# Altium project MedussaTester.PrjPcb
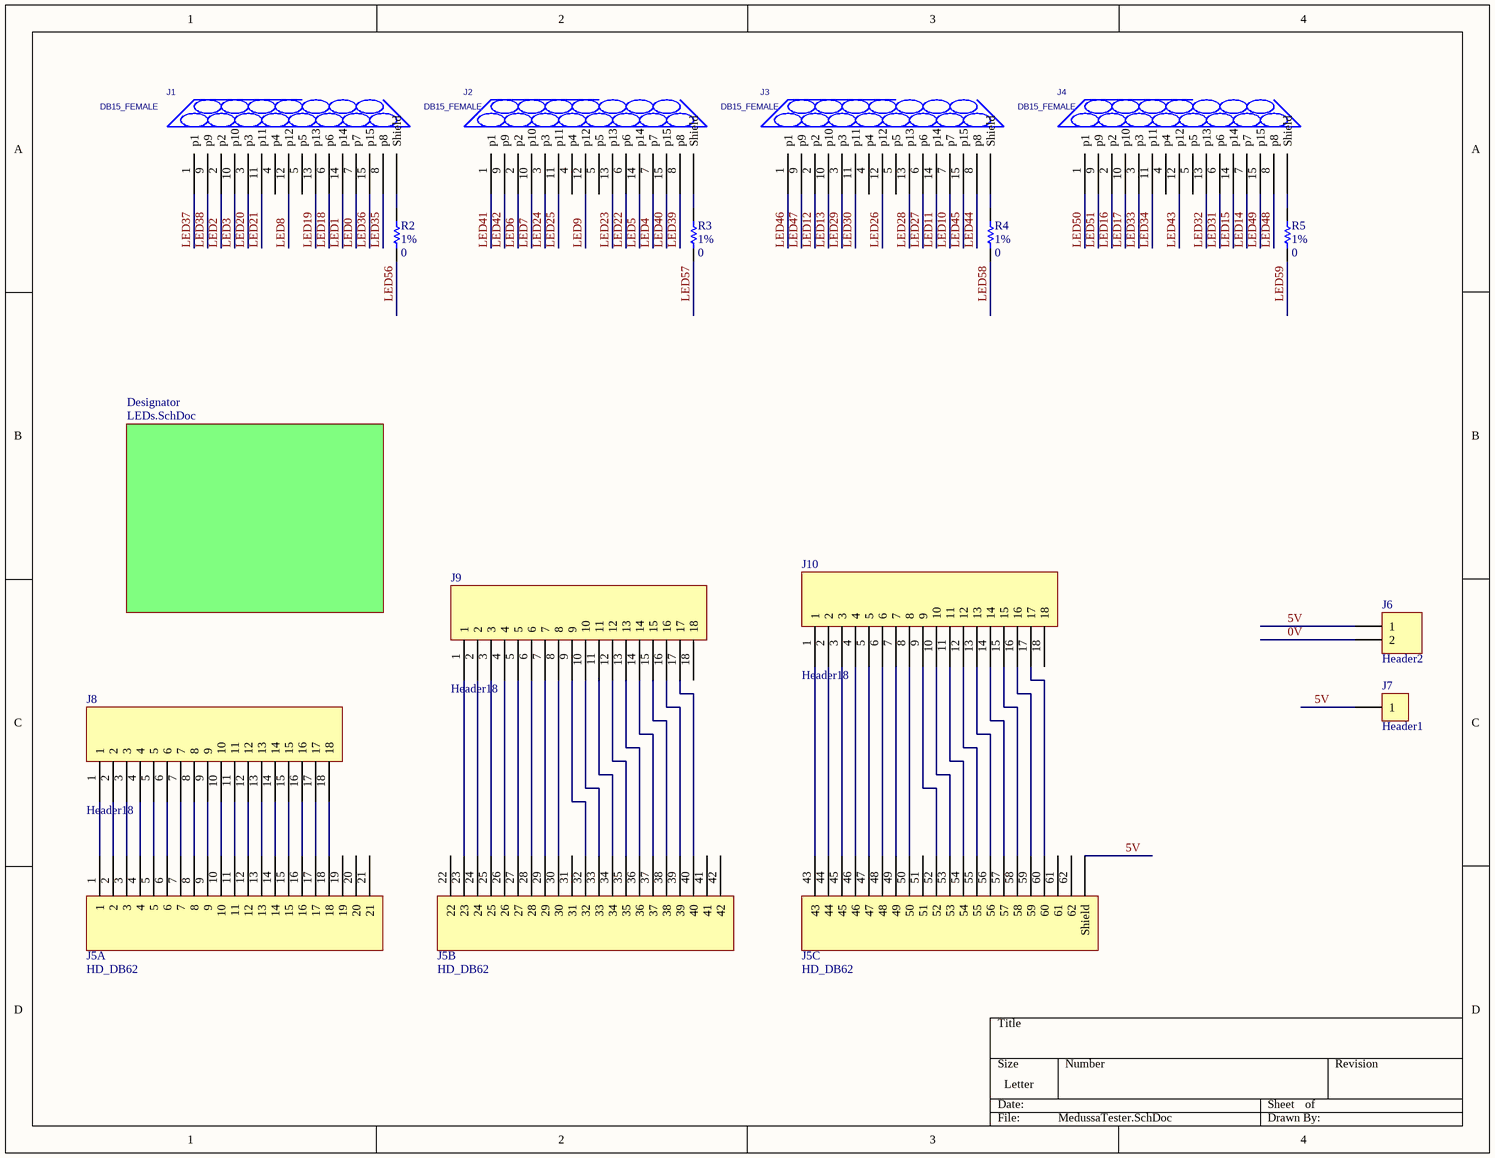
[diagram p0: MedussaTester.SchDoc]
2 sheets, 21 parts. Net scope: global (net labels, ports and power ports of the same name join across sheets).
Board file: MadussaTester.PcbDoc
Sheets:
  MedussaTester.SchDoc
    Designator = LEDs.SchDoc

## Sheet MedussaTester.SchDoc
size Letter

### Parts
J1  DB15_FEMALE  [DSUB/RS.318/TM/15]
J2  DB15_FEMALE  [DSUB/RS.318/TM/15]
J3  DB15_FEMALE  [DSUB/RS.318/TM/15]
J4  DB15_FEMALE  [DSUB/RS.318/TM/15]
J5  HD_DB62  [HD_DB62]  (parts A,B,C of 3)
J6  Header2  [HDR1X2]
J7  Header1  [HDR1]
J8  Header18  [HDR1X18]
J9  Header18  [HDR1X18]
J10  Header18  [HDR1X18]
R2  value 0  Param: 1%  [0603]  (hidden comment: 10k Ohms)
R3  value 0  Param: 1%  [0603]  (hidden comment: 10k Ohms)
R4  value 0  Param: 1%  [0603]  (hidden comment: 10k Ohms)
R5  value 0  Param: 1%  [0603]  (hidden comment: 10k Ohms)

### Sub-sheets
Designator = LEDs.SchDoc: no entries

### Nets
0V: J6.2
5V: J5.HOLE63(Shield) J6.1 J7.1
LED0: J1.7(p7)
LED1: J1.14(p14)
LED2: J1.2(p2)
LED3: J1.10(p10)
LED4: J2.7(p7)
LED5: J2.14(p14)
LED6: J2.2(p2)
LED7: J2.10(p10)
LED8: J1.12(p12)
LED9: J2.12(p12)
LED10: J3.7(p7)
LED11: J3.14(p14)
LED12: J3.2(p2)
LED13: J3.10(p10)
LED14: J4.7(p7)
LED15: J4.14(p14)
LED16: J4.2(p2)
LED17: J4.10(p10)
LED18: J1.6(p6)
LED19: J1.13(p13)
LED20: J1.3(p3)
LED21: J1.11(p11)
LED22: J2.6(p6)
LED23: J2.13(p13)
LED24: J2.3(p3)
LED25: J2.11(p11)
LED26: J3.12(p12)
LED27: J3.6(p6)
LED28: J3.13(p13)
LED29: J3.3(p3)
LED30: J3.11(p11)
LED31: J4.6(p6)
LED32: J4.13(p13)
LED33: J4.3(p3)
LED34: J4.11(p11)
LED35: J1.8(p8)
LED36: J1.15(p15)
LED37: J1.1(p1)
LED38: J1.9(p9)
LED39: J2.8(p8)
LED40: J2.15(p15)
LED41: J2.1(p1)
LED42: J2.9(p9)
LED43: J4.12(p12)
LED44: J3.8(p8)
LED45: J3.15(p15)
LED46: J3.1(p1)
LED47: J3.9(p9)
LED48: J4.8(p8)
LED49: J4.15(p15)
LED50: J4.1(p1)
LED51: J4.9(p9)
LED56: R2.1
LED57: R3.1
LED58: R4.1
LED59: R5.1
NetJ1_Hole30: J1.Hole30(Shield) R2.2
NetJ2_Hole30: J2.Hole30(Shield) R3.2
NetJ3_Hole30: J3.Hole30(Shield) R4.2
NetJ4_Hole30: J4.Hole30(Shield) R5.2
NetJ5_1: J5.1 J8.1
NetJ5_2: J5.2 J8.2
NetJ5_3: J5.3 J8.3
NetJ5_4: J5.4 J8.4
NetJ5_5: J5.5 J8.5
NetJ5_6: J5.6 J8.6
NetJ5_7: J5.7 J8.7
NetJ5_8: J5.8 J8.8
NetJ5_9: J5.9 J8.9
NetJ5_10: J5.10 J8.10
NetJ5_11: J5.11 J8.11
NetJ5_12: J5.12 J8.12
NetJ5_13: J5.13 J8.13
NetJ5_14: J5.14 J8.14
NetJ5_15: J5.15 J8.15
NetJ5_16: J5.16 J8.16
NetJ5_17: J5.17 J8.17
NetJ5_18: J5.18 J8.18
NetJ5_23: J5.23 J9.1
NetJ5_24: J5.24 J9.2
NetJ5_25: J5.25 J9.3
NetJ5_26: J5.26 J9.4
NetJ5_27: J5.27 J9.5
NetJ5_28: J5.28 J9.6
NetJ5_29: J5.29 J9.7
NetJ5_30: J5.30 J9.8
NetJ5_32: J5.32 J9.9
NetJ5_33: J5.33 J9.10
NetJ5_34: J5.34 J9.11
NetJ5_35: J5.35 J9.12
NetJ5_36: J5.36 J9.13
NetJ5_37: J5.37 J9.14
NetJ5_38: J5.38 J9.15
NetJ5_39: J5.39 J9.16
NetJ5_40: J5.40 J9.17
NetJ5_43: J5.43 J10.1
NetJ5_44: J5.44 J10.2
NetJ5_45: J5.45 J10.3
NetJ5_46: J5.46 J10.4
NetJ5_47: J5.47 J10.5
NetJ5_48: J5.48 J10.6
NetJ5_49: J5.49 J10.7
NetJ5_50: J5.50 J10.8
NetJ5_52: J5.52 J10.9
NetJ5_53: J5.53 J10.10
NetJ5_54: J5.54 J10.11
NetJ5_55: J5.55 J10.12
NetJ5_56: J5.56 J10.13
NetJ5_57: J5.57 J10.14
NetJ5_58: J5.58 J10.15
NetJ5_59: J5.59 J10.16
NetJ5_60: J5.60 J10.17

Not connected (* = marked no-connect by the designer): J1 4(p4) 5(p5); J2 4(p4) 5(p5); J3 4(p4) 5(p5); J4 4(p4) 5(p5); J5 19 20 21 22 31 41 42 51 61 62; J9 18; J10 18

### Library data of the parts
J1-J4 = DB15_FEMALE: COMPFIXED: NO; COMPGROUP: 0; COMPHEIGHT: 0.000; COMPLOC: [4502.733,1338.467]; COMPROT: 270; COMPSIDE: TOP
J7 = Header1: TestPoint1
R2-R5 = Res0603: Resistor; Param1: 100ppm/C

## Sheet LEDs.SchDoc
size Letter
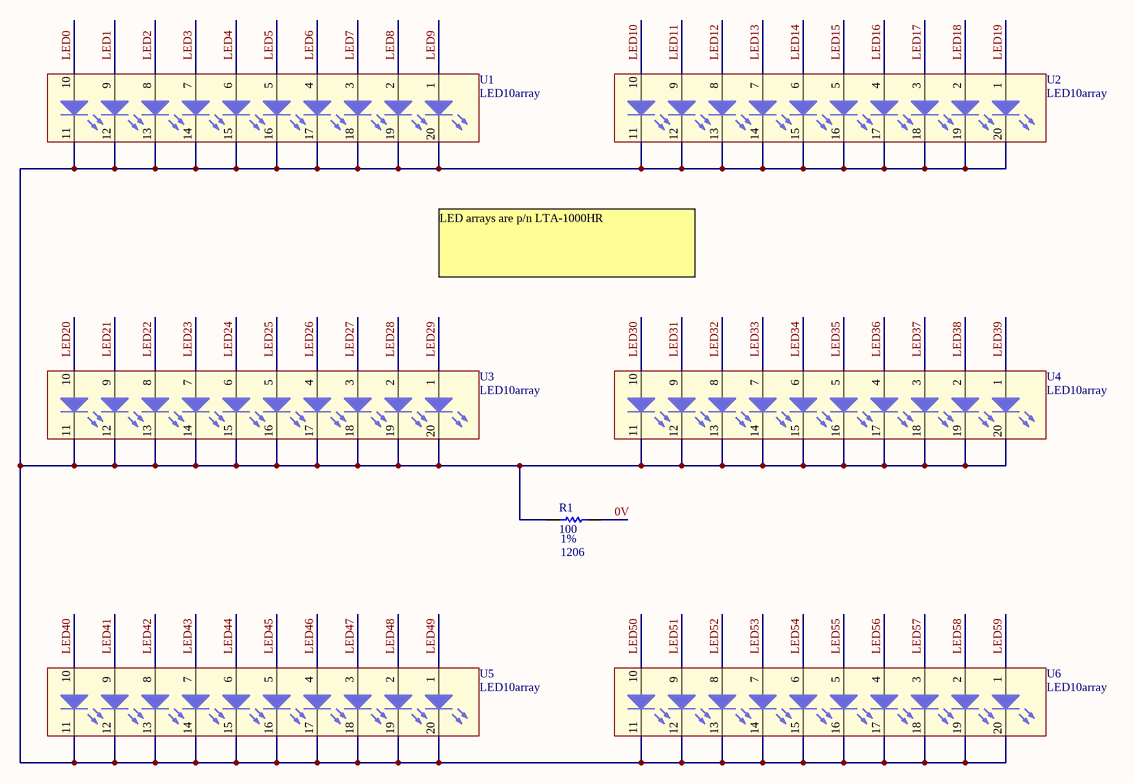
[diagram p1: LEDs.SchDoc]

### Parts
R1  100  Param: 1%  [1206]
U1  LED10array  [LED10array]
U2  LED10array  [LED10array]
U3  LED10array  [LED10array]
U4  LED10array  [LED10array]
U5  LED10array  [LED10array]
U6  LED10array  [LED10array]

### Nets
0V: R1.2
LED0: U1.10
LED1: U1.9
LED2: U1.8
LED3: U1.7
LED4: U1.6
LED5: U1.5
LED6: U1.4
LED7: U1.3
LED8: U1.2
LED9: U1.1
LED10: U2.10
LED11: U2.9
LED12: U2.8
LED13: U2.7
LED14: U2.6
LED15: U2.5
LED16: U2.4
LED17: U2.3
LED18: U2.2
LED19: U2.1
LED20: U3.10
LED21: U3.9
LED22: U3.8
LED23: U3.7
LED24: U3.6
LED25: U3.5
LED26: U3.4
LED27: U3.3
LED28: U3.2
LED29: U3.1
LED30: U4.10
LED31: U4.9
LED32: U4.8
LED33: U4.7
LED34: U4.6
LED35: U4.5
LED36: U4.4
LED37: U4.3
LED38: U4.2
LED39: U4.1
LED40: U5.10
LED41: U5.9
LED42: U5.8
LED43: U5.7
LED44: U5.6
LED45: U5.5
LED46: U5.4
LED47: U5.3
LED48: U5.2
LED49: U5.1
LED50: U6.10
LED51: U6.9
LED52: U6.8
LED53: U6.7
LED54: U6.6
LED55: U6.5
LED56: U6.4
LED57: U6.3
LED58: U6.2
LED59: U6.1
NetR1_1: R1.1 U1.11 U1.12 U1.13 U1.14 U1.15 U1.16 U1.17 U1.18 U1.19 U1.20 U2.11 U2.12 U2.13 U2.14 U2.15 U2.16 U2.17 U2.18 U2.19 U2.20 U3.11 U3.12 U3.13 U3.14 U3.15 U3.16 U3.17 U3.18 U3.19 U3.20 U4.11 U4.12 U4.13 U4.14 U4.15 U4.16 U4.17 U4.18 U4.19 U4.20 U5.11 U5.12 U5.13 U5.14 U5.15 U5.16 U5.17 U5.18 U5.19 U5.20 U6.11 U6.12 U6.13 U6.14 U6.15 U6.16 U6.17 U6.18 U6.19 U6.20

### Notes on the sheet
- LED arrays are p/n LTA-1000HR

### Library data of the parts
R1 = Res1206: Resistor; Param1: 100ppm/C; Value: DNL

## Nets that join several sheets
0V: MedussaTester (J6.2), LEDs (R1.2)
LED0: MedussaTester (J1.7), LEDs (U1.10)
LED1: MedussaTester (J1.14), LEDs (U1.9)
LED2: MedussaTester (J1.2), LEDs (U1.8)
LED3: MedussaTester (J1.10), LEDs (U1.7)
LED4: MedussaTester (J2.7), LEDs (U1.6)
LED5: MedussaTester (J2.14), LEDs (U1.5)
LED6: MedussaTester (J2.2), LEDs (U1.4)
LED7: MedussaTester (J2.10), LEDs (U1.3)
LED8: MedussaTester (J1.12), LEDs (U1.2)
LED9: MedussaTester (J2.12), LEDs (U1.1)
LED10: MedussaTester (J3.7), LEDs (U2.10)
LED11: MedussaTester (J3.14), LEDs (U2.9)
LED12: MedussaTester (J3.2), LEDs (U2.8)
LED13: MedussaTester (J3.10), LEDs (U2.7)
LED14: MedussaTester (J4.7), LEDs (U2.6)
LED15: MedussaTester (J4.14), LEDs (U2.5)
LED16: MedussaTester (J4.2), LEDs (U2.4)
LED17: MedussaTester (J4.10), LEDs (U2.3)
LED18: MedussaTester (J1.6), LEDs (U2.2)
LED19: MedussaTester (J1.13), LEDs (U2.1)
LED20: MedussaTester (J1.3), LEDs (U3.10)
LED21: MedussaTester (J1.11), LEDs (U3.9)
LED22: MedussaTester (J2.6), LEDs (U3.8)
LED23: MedussaTester (J2.13), LEDs (U3.7)
LED24: MedussaTester (J2.3), LEDs (U3.6)
LED25: MedussaTester (J2.11), LEDs (U3.5)
LED26: MedussaTester (J3.12), LEDs (U3.4)
LED27: MedussaTester (J3.6), LEDs (U3.3)
LED28: MedussaTester (J3.13), LEDs (U3.2)
LED29: MedussaTester (J3.3), LEDs (U3.1)
LED30: MedussaTester (J3.11), LEDs (U4.10)
LED31: MedussaTester (J4.6), LEDs (U4.9)
LED32: MedussaTester (J4.13), LEDs (U4.8)
LED33: MedussaTester (J4.3), LEDs (U4.7)
LED34: MedussaTester (J4.11), LEDs (U4.6)
LED35: MedussaTester (J1.8), LEDs (U4.5)
LED36: MedussaTester (J1.15), LEDs (U4.4)
LED37: MedussaTester (J1.1), LEDs (U4.3)
LED38: MedussaTester (J1.9), LEDs (U4.2)
LED39: MedussaTester (J2.8), LEDs (U4.1)
LED40: MedussaTester (J2.15), LEDs (U5.10)
LED41: MedussaTester (J2.1), LEDs (U5.9)
LED42: MedussaTester (J2.9), LEDs (U5.8)
LED43: MedussaTester (J4.12), LEDs (U5.7)
LED44: MedussaTester (J3.8), LEDs (U5.6)
LED45: MedussaTester (J3.15), LEDs (U5.5)
LED46: MedussaTester (J3.1), LEDs (U5.4)
LED47: MedussaTester (J3.9), LEDs (U5.3)
LED48: MedussaTester (J4.8), LEDs (U5.2)
LED49: MedussaTester (J4.15), LEDs (U5.1)
LED50: MedussaTester (J4.1), LEDs (U6.10)
LED51: MedussaTester (J4.9), LEDs (U6.9)
LED56: MedussaTester (R2.1), LEDs (U6.4)
LED57: MedussaTester (R3.1), LEDs (U6.3)
LED58: MedussaTester (R4.1), LEDs (U6.2)
LED59: MedussaTester (R5.1), LEDs (U6.1)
